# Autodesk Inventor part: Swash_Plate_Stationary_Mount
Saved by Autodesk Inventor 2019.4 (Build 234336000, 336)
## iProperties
Created: 2020-02
Part Number: Swash_Plate_Stationary_Mount
Material: Generic
Document SubType Name: Modeling
Designer: Administrator
Density: 1 g/cm^3
Appearance: Default
Title: Swash_Plate_Stationary_Mount v3
Author: Administrator
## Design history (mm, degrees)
feature "Body1"
feature "Body2"
body "Solid1"
body "Solid2"
